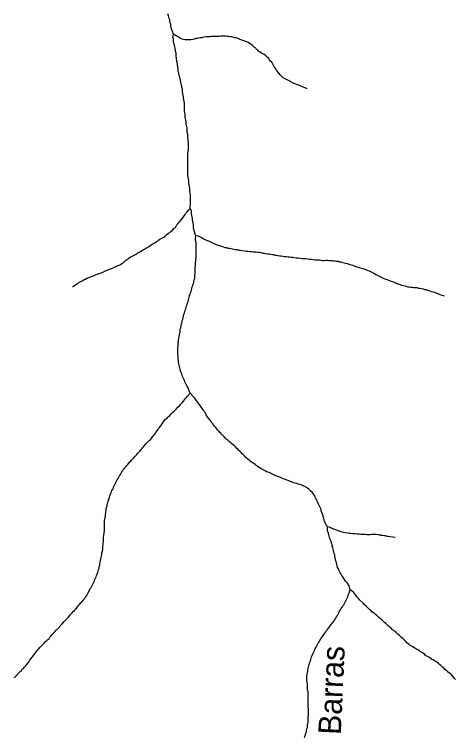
# Model space of a CAD drawing. Extents: x 652.3 to 678, y 7316.9 to 7344.9.
# Drawn here: x 673.932 to 675.495, y 7319.614 to 7322.173 of the extents above; entities that cross this region are included whole.
import ezdxf
from ezdxf.enums import TextEntityAlignment as Align

# ---------------------------------------------------------------- set-up
doc = ezdxf.new("R2010")
doc.units = 0
doc.header["$LTSCALE"] = 0.032
doc.layers.add('61', color=7, linetype='Continuous')
doc.layers.add('7', color=7, linetype='Continuous', lineweight=25)

msp = doc.modelspace()

# ---------------------------------------------------------------- linework, layer by layer
at = {"layer": '7'}
for p, q in [((674.5746, 7321.3896), (674.5741, 7321.3909)), ((674.5547, 7320.8302), (674.546, 7320.8517))]:
    msp.add_line(p, q, dxfattribs=at)
for points in [[(674.495, 7322.1025), (674.4879, 7322.1216), (674.4863, 7322.1327), (674.4855, 7322.1383), (674.4839, 7322.1431), (674.4831, 7322.1487), (674.4823, 7322.1542), (674.4807, 7322.159), (674.4791, 7322.1638), (674.4775, 7322.1685), (674.4759, 7322.1749)], [(674.5117, 7321.9816), (674.511, 7321.9871), (674.5102, 7321.9935), (674.5094, 7321.9991), (674.5078, 7322.0038), (674.5078, 7322.0094), (674.5062, 7322.0142), (674.5062, 7322.0198), (674.5054, 7322.0253), (674.5054, 7322.0309), (674.5046, 7322.0365), (674.503, 7322.042), (674.5022, 7322.0476), (674.5014, 7322.0532), (674.4998, 7322.0579), (674.499, 7322.0635), (674.4982, 7322.0691), (674.4958, 7322.0739), (674.4958, 7322.0794), (674.495, 7322.085), (674.4934, 7322.0906), (674.495, 7322.1025)], [(674.9693, 7321.9097), (674.9689, 7321.9098), (674.9645, 7321.9115), (674.9502, 7321.9171), (674.9454, 7321.9195), (674.9311, 7321.9243), (674.9215, 7321.929), (674.9168, 7321.9306), (674.9128, 7321.9338), (674.8985, 7321.941), (674.8937, 7321.9434), (674.8889, 7321.9458), (674.8849, 7321.9489), (674.8809, 7321.9521), (674.877, 7321.9553), (674.8738, 7321.9593), (674.8698, 7321.9633), (674.8603, 7321.9752), (674.8579, 7321.98), (674.8515, 7321.9895), (674.8483, 7321.9943), (674.8436, 7322.0038), (674.8396, 7322.0078), (674.8364, 7322.0126), (674.8332, 7322.0166), (674.8253, 7322.0245), (674.8213, 7322.0277), (674.8173, 7322.0309), (674.8077, 7322.0357), (674.803, 7322.0388), (674.7982, 7322.042), (674.7942, 7322.046), (674.7902, 7322.0492), (674.7871, 7322.0532), (674.7831, 7322.0564), (674.7791, 7322.0595), (674.7751, 7322.0635), (674.7703, 7322.0667), (674.7656, 7322.0699), (674.7608, 7322.0731), (674.756, 7322.0754), (674.7513, 7322.077), (674.7465, 7322.0794), (674.7417, 7322.081), (674.7322, 7322.0842), (674.7274, 7322.0866), (674.7178, 7322.0898), (674.7123, 7322.0906), (674.7075, 7322.0922), (674.7019, 7322.0937), (674.6956, 7322.0937), (674.6908, 7322.0953), (674.6852, 7322.0953), (674.6796, 7322.0961), (674.6629, 7322.0961), (674.6574, 7322.0953), (674.6295, 7322.0953), (674.6239, 7322.0937), (674.6128, 7322.0937), (674.6017, 7322.0922), (674.5961, 7322.0906), (674.5905, 7322.0906), (674.5857, 7322.089), (674.5802, 7322.0882), (674.5746, 7322.0874), (674.5698, 7322.0858), (674.5643, 7322.0842), (674.5587, 7322.0834), (674.5531, 7322.0826), (674.542, 7322.0826), (674.5364, 7322.0834), (674.5308, 7322.0842), (674.5261, 7322.0858), (674.5165, 7322.0906), (674.5094, 7322.0945), (674.5054, 7322.0977), (674.495, 7322.1025)], [(674.5547, 7321.4858), (674.5555, 7321.5049), (674.5563, 7321.5161), (674.5563, 7321.5216), (674.5563, 7321.5272), (674.5555, 7321.5328), (674.5547, 7321.5392), (674.5539, 7321.5447), (674.5531, 7321.5503), (674.5531, 7321.5559), (674.5523, 7321.5622), (674.5515, 7321.5678), (674.5499, 7321.5734), (674.5499, 7321.5789), (674.5499, 7321.5845), (674.5491, 7321.5901), (674.5476, 7321.5964), (674.5468, 7321.602), (674.5468, 7321.6076), (674.5468, 7321.6132), (674.5468, 7321.6187), (674.5468, 7321.6243), (674.5468, 7321.6299), (674.5468, 7321.6354), (674.5468, 7321.641), (674.5468, 7321.6466), (674.5468, 7321.6521), (674.5468, 7321.6577), (674.5468, 7321.6633), (674.5468, 7321.6689), (674.5468, 7321.6744), (674.5468, 7321.68), (674.5476, 7321.6872), (674.5484, 7321.6927), (674.5491, 7321.6983), (674.5484, 7321.7039), (674.5484, 7321.7094), (674.5484, 7321.715), (674.5484, 7321.7206), (674.5476, 7321.7261), (674.5476, 7321.7317), (674.5468, 7321.7373), (674.5468, 7321.7429), (674.546, 7321.7492), (674.5444, 7321.754), (674.5444, 7321.7596), (674.5436, 7321.7651), (674.5436, 7321.7707), (674.5428, 7321.7763), (674.5412, 7321.781), (674.5404, 7321.7866), (674.5404, 7321.7922), (674.5396, 7321.7978), (674.538, 7321.8025), (674.5372, 7321.8081), (674.5372, 7321.8137), (674.5364, 7321.8192), (674.5356, 7321.8248), (674.5348, 7321.8312), (674.5348, 7321.8367), (674.534, 7321.8423), (674.534, 7321.8479), (674.534, 7321.8535), (674.534, 7321.859), (674.5332, 7321.8646), (674.5316, 7321.8702), (674.5308, 7321.8757), (674.5308, 7321.8813), (674.53, 7321.8869), (674.5285, 7321.8916), (674.5277, 7321.8972), (674.5277, 7321.9028), (674.5269, 7321.9084), (674.5253, 7321.9131), (674.5245, 7321.9187), (674.5237, 7321.9243), (674.5221, 7321.929), (674.5213, 7321.9346), (674.5205, 7321.9402), (674.5189, 7321.945), (674.5181, 7321.9505), (674.5165, 7321.9553), (674.5149, 7321.9601), (674.5141, 7321.9656), (674.5125, 7321.9704), (674.5117, 7321.976), (674.5117, 7321.9816)], [(674.1379, 7321.2083), (674.1385, 7321.2088), (674.1425, 7321.2113), (674.1513, 7321.2169), (674.1561, 7321.2193), (674.1601, 7321.2225), (674.1648, 7321.2257), (674.1696, 7321.228), (674.1744, 7321.2304), (674.1784, 7321.2336), (674.1831, 7321.2352), (674.1879, 7321.2384), (674.2022, 7321.2432), (674.207, 7321.2455), (674.2118, 7321.2471), (674.2165, 7321.2487), (674.2213, 7321.2511), (674.2356, 7321.2559), (674.2404, 7321.2575), (674.2452, 7321.2599), (674.25, 7321.2623), (674.2547, 7321.2638), (674.2595, 7321.2662), (674.2643, 7321.2678), (674.2691, 7321.2702), (674.2738, 7321.2718), (674.2834, 7321.2766), (674.2882, 7321.2782), (674.2977, 7321.2829), (674.3025, 7321.2845), (674.3073, 7321.2869), (674.312, 7321.2901), (674.3168, 7321.2925), (674.3248, 7321.3004), (674.3287, 7321.3036), (674.3335, 7321.306), (674.3375, 7321.3092), (674.3423, 7321.3124), (674.347, 7321.3148), (674.351, 7321.318), (674.3653, 7321.3251), (674.3693, 7321.3283), (674.3789, 7321.3331), (674.3836, 7321.3363), (674.3884, 7321.3386), (674.3932, 7321.341), (674.3972, 7321.3442), (674.4067, 7321.349), (674.4107, 7321.3522), (674.4155, 7321.3554), (674.4202, 7321.3585), (674.425, 7321.3609), (674.429, 7321.3641), (674.4338, 7321.3673), (674.4385, 7321.3697), (674.4425, 7321.3729), (674.4473, 7321.376), (674.4521, 7321.3784), (674.4568, 7321.3816), (674.4616, 7321.384), (674.4656, 7321.3872), (674.4696, 7321.3904), (674.4736, 7321.3943), (674.4775, 7321.3975), (674.4823, 7321.4007), (674.4863, 7321.4039), (674.4903, 7321.4071), (674.4982, 7321.415), (674.5022, 7321.4182), (674.5054, 7321.4222), (674.5078, 7321.427), (674.511, 7321.4309), (674.5141, 7321.4357), (674.5181, 7321.4397), (674.5213, 7321.4437), (674.5285, 7321.4524), (674.5332, 7321.4596), (674.5364, 7321.4636), (674.5396, 7321.4683), (674.5428, 7321.4723), (674.5495, 7321.4805), (674.5547, 7321.4858)], [(674.5741, 7321.3909), (674.5674, 7321.411), (674.5667, 7321.4166), (674.5659, 7321.4222), (674.5659, 7321.4278), (674.5651, 7321.4333), (674.5635, 7321.4389), (674.5627, 7321.4445), (674.5627, 7321.45), (674.5619, 7321.4556), (674.5603, 7321.4604), (674.5595, 7321.466), (674.5595, 7321.4715), (674.5595, 7321.4771), (674.5547, 7321.4858)], [(674.546, 7320.8517), (674.5428, 7320.8565), (674.5404, 7320.8612), (674.538, 7320.866), (674.5356, 7320.8708), (674.534, 7320.8756), (674.5316, 7320.8803), (674.5293, 7320.8851), (674.5277, 7320.8899), (674.5261, 7320.8946), (674.5245, 7320.8994), (674.5229, 7320.9042), (674.5205, 7320.909), (674.5197, 7320.9145), (674.5181, 7320.9193), (674.5165, 7320.9249), (674.5157, 7320.9305), (674.5141, 7320.9352), (674.5133, 7320.9408), (674.5133, 7320.9464), (674.5125, 7320.9527), (674.5125, 7320.9583), (674.5117, 7320.9639), (674.511, 7320.9694), (674.511, 7320.975), (674.511, 7320.9806), (674.511, 7320.9862), (674.511, 7320.9917), (674.5117, 7320.9973), (674.5125, 7321.0029), (674.5125, 7321.0084), (674.5133, 7321.014), (674.5133, 7321.0196), (674.5141, 7321.0251), (674.5157, 7321.0299), (674.5165, 7321.0355), (674.5173, 7321.0411), (674.5189, 7321.0458), (674.5197, 7321.0514), (674.5197, 7321.057), (674.5213, 7321.0625), (674.5229, 7321.0681), (674.5229, 7321.0737), (674.5245, 7321.0785), (674.5261, 7321.0832), (674.5261, 7321.0888), (674.5285, 7321.0936), (674.5293, 7321.0991), (674.5308, 7321.1047), (674.5324, 7321.1095), (674.534, 7321.1151), (674.5356, 7321.1198), (674.5372, 7321.1254), (674.5388, 7321.1302), (674.5404, 7321.1357), (674.542, 7321.1405), (674.5444, 7321.1453), (674.5452, 7321.1509), (674.5476, 7321.1556), (674.5484, 7321.1612), (674.5499, 7321.166), (674.5515, 7321.1708), (674.5523, 7321.1763), (674.5547, 7321.1811), (674.5563, 7321.1867), (674.5579, 7321.1914), (674.5595, 7321.197), (674.5611, 7321.2018), (674.5619, 7321.2074), (674.5643, 7321.2121), (674.5651, 7321.2177), (674.5674, 7321.2225), (674.5674, 7321.228), (674.569, 7321.2328), (674.5706, 7321.2376), (674.5706, 7321.2432), (674.5706, 7321.2487), (674.5722, 7321.2535), (674.5722, 7321.2599), (674.5722, 7321.2654), (674.5722, 7321.271), (674.5722, 7321.2766), (674.573, 7321.2821), (674.5738, 7321.2877), (674.5738, 7321.2933), (674.5746, 7321.2989), (674.5746, 7321.3044), (674.5754, 7321.31), (674.5754, 7321.3156), (674.5754, 7321.3211), (674.5754, 7321.3267), (674.5762, 7321.3323), (674.5762, 7321.3378), (674.5762, 7321.3434), (674.5754, 7321.349), (674.5754, 7321.3546), (674.5754, 7321.3601), (674.5754, 7321.3657), (674.5738, 7321.3713), (674.573, 7321.3776), (674.5746, 7321.3896)], [(674.5746, 7321.3896), (674.5826, 7321.3888), (674.5873, 7321.3864), (674.5921, 7321.3832), (674.5969, 7321.3808), (674.604, 7321.3768), (674.6152, 7321.3721), (674.62, 7321.3705), (674.6247, 7321.3681), (674.6438, 7321.3585), (674.6534, 7321.3554), (674.659, 7321.3538), (674.6733, 7321.349), (674.678, 7321.3474), (674.6836, 7321.3466), (674.6884, 7321.345), (674.694, 7321.3442), (674.6995, 7321.3434), (674.7051, 7321.3426), (674.7099, 7321.341), (674.7154, 7321.3402), (674.721, 7321.3394), (674.7266, 7321.3378), (674.7322, 7321.337), (674.7377, 7321.3363), (674.7489, 7321.3347), (674.7544, 7321.3339), (674.76, 7321.3339), (674.7656, 7321.3331), (674.7719, 7321.3323), (674.7775, 7321.3315), (674.7886, 7321.3315), (674.795, 7321.3307), (674.8006, 7321.3299), (674.8069, 7321.3291), (674.8117, 7321.3275), (674.8173, 7321.3275), (674.8229, 7321.3259)], [(674.8229, 7321.3259), (674.8284, 7321.3251), (674.8348, 7321.3243), (674.8404, 7321.3235), (674.8451, 7321.3219), (674.8507, 7321.3219), (674.8555, 7321.3203), (674.8611, 7321.3203), (674.8658, 7321.3187), (674.8722, 7321.318), (674.8778, 7321.318), (674.8833, 7321.3164), (674.8889, 7321.3156), (674.8961, 7321.3148), (674.9016, 7321.314), (674.9072, 7321.314), (674.9128, 7321.3132), (674.9183, 7321.3124), (674.9247, 7321.3116), (674.9303, 7321.3108), (674.9359, 7321.3108), (674.947, 7321.3092), (674.9534, 7321.3084), (674.9589, 7321.3084), (674.9645, 7321.3076), (674.9717, 7321.3068), (674.9772, 7321.306), (674.9844, 7321.3052), (674.99, 7321.3044), (674.9963, 7321.3036), (675.0019, 7321.3028), (675.013, 7321.3028), (675.0186, 7321.302), (675.0242, 7321.3012), (675.0297, 7321.3012), (675.0353, 7321.302), (675.0409, 7321.302), (675.0465, 7321.3012), (675.052, 7321.3012), (675.0576, 7321.3004), (675.0632, 7321.2997), (675.0687, 7321.2997), (675.0735, 7321.2981), (675.0799, 7321.2981), (675.0846, 7321.2965), (675.0902, 7321.2957), (675.0958, 7321.2941), (675.1006, 7321.2925), (675.1061, 7321.2917), (675.1117, 7321.2901), (675.1212, 7321.2869), (675.1268, 7321.2861), (675.1316, 7321.2845), (675.1364, 7321.2821), (675.1459, 7321.279), (675.1507, 7321.2774), (675.165, 7321.2726), (675.1698, 7321.271), (675.1793, 7321.2678), (675.1841, 7321.2654), (675.1889, 7321.2638), (675.1937, 7321.2615), (675.1984, 7321.2599), (675.2032, 7321.2567), (675.208, 7321.2551), (675.2128, 7321.2519), (675.2223, 7321.2471), (675.2271, 7321.244), (675.2414, 7321.2368), (675.2557, 7321.232), (675.2613, 7321.2296), (675.2661, 7321.228), (675.2756, 7321.2249), (675.2852, 7321.2201), (675.2947, 7321.2169), (675.2995, 7321.2153), (675.3043, 7321.2137), (675.3098, 7321.2129), (675.3154, 7321.2113), (675.3202, 7321.2097), (675.3257, 7321.2081), (675.3313, 7321.2074), (675.3369, 7321.2066), (675.3424, 7321.2066), (675.3472, 7321.205), (675.3584, 7321.205), (675.3639, 7321.2034), (675.3695, 7321.2026), (675.3751, 7321.2018), (675.3806, 7321.2002), (675.3854, 7321.1986), (675.391, 7321.1978), (675.3966, 7321.1962), (675.4109, 7321.1914), (675.4157, 7321.1898), (675.4204, 7321.1883), (675.4252, 7321.1859), (675.4347, 7321.1827), (675.4395, 7321.1803), (675.4546, 7321.1755), (675.455, 7321.1754)], [(674.2571, 7320.4156), (674.2571, 7320.422), (674.2603, 7320.4316), (674.2603, 7320.4371), (674.2627, 7320.4419), (674.2635, 7320.4475), (674.2683, 7320.4618), (674.2699, 7320.4666), (674.273, 7320.4761), (674.2754, 7320.4809), (674.277, 7320.4857), (674.2802, 7320.4904), (674.2826, 7320.4952), (674.2842, 7320.5), (674.2866, 7320.5048), (674.2937, 7320.5191), (674.2961, 7320.5239), (674.2993, 7320.5286), (674.3041, 7320.5382), (674.3073, 7320.543), (674.3096, 7320.5477), (674.316, 7320.5573), (674.32, 7320.5613), (674.3232, 7320.566), (674.3264, 7320.57), (674.3295, 7320.574), (674.3335, 7320.578), (674.3399, 7320.5859), (674.3439, 7320.5899), (674.347, 7320.5939), (674.351, 7320.5979), (674.355, 7320.6018), (674.3582, 7320.6058), (674.3622, 7320.6098), (674.3653, 7320.6138), (674.3693, 7320.6177), (674.3757, 7320.6257), (674.3797, 7320.6297), (674.3828, 7320.6337), (674.386, 7320.6376), (674.39, 7320.6416), (674.3964, 7320.6496), (674.4083, 7320.6615), (674.4123, 7320.6647), (674.425, 7320.6806), (674.4282, 7320.6846), (674.4314, 7320.6894), (674.4346, 7320.6941), (674.4409, 7320.7021), (674.4441, 7320.7069), (674.4505, 7320.7148), (674.46, 7320.7291), (674.4664, 7320.7371), (674.4744, 7320.7451), (674.4783, 7320.7482), (674.4823, 7320.7522), (674.4855, 7320.7562), (674.4895, 7320.7594), (674.4934, 7320.7634), (674.4974, 7320.7673), (674.5014, 7320.7705), (674.5054, 7320.7745), (674.5086, 7320.7785), (674.5125, 7320.7825), (674.5165, 7320.7856), (674.5197, 7320.7896), (674.5237, 7320.7936), (674.5269, 7320.7976), (674.538, 7320.8119), (674.542, 7320.8159), (674.5452, 7320.8199), (674.5547, 7320.8302)], [(674.9661, 7320.4968), (674.9621, 7320.5), (674.9573, 7320.5016), (674.9526, 7320.504), (674.9478, 7320.5056), (674.943, 7320.5071), (674.9374, 7320.5087), (674.9319, 7320.5103), (674.9271, 7320.5119), (674.9215, 7320.5127), (674.9168, 7320.5151), (674.912, 7320.5167), (674.9072, 7320.5191), (674.9016, 7320.5207), (674.8969, 7320.5223), (674.8921, 7320.5247), (674.8873, 7320.5262), (674.8825, 7320.5278), (674.8778, 7320.5302), (674.873, 7320.5326), (674.8682, 7320.5342), (674.8634, 7320.5366), (674.8587, 7320.5382), (674.8539, 7320.5406), (674.8491, 7320.543), (674.8443, 7320.5445), (674.8396, 7320.5469), (674.8348, 7320.5493), (674.83, 7320.5509), (674.8253, 7320.5525), (674.8205, 7320.5557), (674.8157, 7320.5573), (674.8109, 7320.5597), (674.8062, 7320.5628), (674.8014, 7320.566), (674.7966, 7320.5684), (674.7926, 7320.5716), (674.7886, 7320.5748), (674.7847, 7320.578), (674.7807, 7320.5811), (674.7759, 7320.5835), (674.7719, 7320.5867), (674.7672, 7320.5899), (674.7632, 7320.5931), (674.7592, 7320.5971), (674.7552, 7320.6002), (674.7513, 7320.6042), (674.7473, 7320.6082), (674.7433, 7320.6122), (674.7393, 7320.6162), (674.7353, 7320.6201), (674.7314, 7320.6241), (674.7274, 7320.6281), (674.7234, 7320.6321), (674.7194, 7320.636), (674.7154, 7320.64), (674.7115, 7320.644), (674.7067, 7320.6472), (674.7027, 7320.6512), (674.6987, 7320.6551), (674.694, 7320.6583), (674.69, 7320.6623), (674.686, 7320.6663), (674.6812, 7320.6695), (674.6773, 7320.6734), (674.6733, 7320.6774), (674.6701, 7320.6814), (674.6661, 7320.6846), (674.6629, 7320.6886), (674.659, 7320.6925), (674.6558, 7320.6965), (674.6518, 7320.7005), (674.6486, 7320.7045), (674.6454, 7320.7085), (674.6414, 7320.7124), (674.6383, 7320.7172), (674.6351, 7320.722), (674.6319, 7320.726), (674.6287, 7320.7299), (674.6255, 7320.7347), (674.6223, 7320.7387), (674.6192, 7320.7427), (674.616, 7320.7474), (674.6128, 7320.7522), (674.6096, 7320.757), (674.608, 7320.7618), (674.6048, 7320.7657), (674.6017, 7320.7705), (674.5985, 7320.7753), (674.5953, 7320.7801), (674.5921, 7320.784), (674.5889, 7320.7888), (674.5857, 7320.7928), (674.5826, 7320.7968), (674.5794, 7320.8008), (674.5762, 7320.8055), (674.573, 7320.8095), (674.5698, 7320.8143), (674.5667, 7320.8183), (674.5547, 7320.8302)], [(675.0409, 7320.3568), (675.0398, 7320.3587), (675.0305, 7320.3759), (675.0297, 7320.3814), (675.0289, 7320.387), (675.0266, 7320.3918), (675.0258, 7320.3973), (675.0234, 7320.4021), (675.0218, 7320.4077), (675.0194, 7320.4125), (675.0186, 7320.418), (675.0162, 7320.4228), (675.0138, 7320.4276), (675.0122, 7320.4331), (675.0098, 7320.4379), (675.0075, 7320.4427), (675.0051, 7320.4475), (675.0035, 7320.4522), (675.0003, 7320.457), (674.9979, 7320.4618), (674.9963, 7320.4666), (674.9931, 7320.4713), (674.99, 7320.4761), (674.9868, 7320.4801), (674.9828, 7320.4833), (674.9788, 7320.4865), (674.9748, 7320.4904), (674.9701, 7320.4936), (674.9661, 7320.4968)], [(673.9316, 7319.8223), (673.9318, 7319.8226), (673.9373, 7319.8284), (673.9484, 7319.8404), (673.9524, 7319.8443), (673.9564, 7319.8483), (673.9595, 7319.8523), (673.9635, 7319.8555), (673.9667, 7319.8595), (673.9707, 7319.8634), (673.9739, 7319.8674), (673.9802, 7319.8754), (673.9834, 7319.8801), (673.9866, 7319.8849), (673.9898, 7319.8897), (673.9993, 7319.9016), (674.0025, 7319.9056), (674.0057, 7319.9104), (674.0089, 7319.9144), (674.0121, 7319.9183), (674.0152, 7319.9223), (674.0232, 7319.9303), (674.0264, 7319.9343), (674.0383, 7319.9462), (674.0423, 7319.9502), (674.0463, 7319.9541), (674.0502, 7319.9573), (674.0542, 7319.9613), (674.0574, 7319.9661), (674.0606, 7319.9701), (674.0646, 7319.974), (674.0678, 7319.978), (674.0757, 7319.986), (674.0789, 7319.9899), (674.0908, 7320.0019), (674.094, 7320.0059), (674.0972, 7320.0098), (674.1012, 7320.013), (674.1075, 7320.021), (674.1115, 7320.025), (674.1147, 7320.0289), (674.1227, 7320.0369), (674.129, 7320.0449), (674.133, 7320.0488), (674.1362, 7320.0528), (674.1402, 7320.0568), (674.1441, 7320.0608), (674.1473, 7320.0647), (674.1513, 7320.0687), (674.1577, 7320.0767), (674.1616, 7320.0807), (674.168, 7320.0886), (674.1712, 7320.0926), (674.1752, 7320.0966), (674.1784, 7320.1006), (674.1815, 7320.1053), (674.1847, 7320.1093), (674.1879, 7320.1141), (674.1903, 7320.1189), (674.1935, 7320.1236), (674.1959, 7320.1284), (674.199, 7320.1332), (674.2006, 7320.1379), (674.2038, 7320.1419), (674.211, 7320.1562), (674.2126, 7320.161), (674.215, 7320.1658), (674.2165, 7320.1706), (674.2189, 7320.1753), (674.2213, 7320.1801), (674.2229, 7320.1849), (674.2253, 7320.1897), (674.2269, 7320.1952), (674.2285, 7320.2), (674.2301, 7320.2056), (674.2317, 7320.2104), (674.2325, 7320.2159), (674.2341, 7320.2207), (674.2348, 7320.2263), (674.2356, 7320.2318), (674.2372, 7320.2366), (674.2388, 7320.2478), (674.2404, 7320.2533), (674.2412, 7320.2597), (674.242, 7320.2653), (674.2436, 7320.2708), (674.2444, 7320.2764), (674.2444, 7320.2883), (674.246, 7320.2931), (674.246, 7320.2987), (674.2476, 7320.3035), (674.2476, 7320.3202), (674.2484, 7320.3257), (674.25, 7320.3369), (674.2508, 7320.3424), (674.2508, 7320.3767), (674.2524, 7320.3878), (674.2539, 7320.3926), (674.2539, 7320.3981), (674.2555, 7320.4093), (674.2571, 7320.4156)], [(675.2815, 7320.3189), (675.2811, 7320.319), (675.2732, 7320.3202), (675.2629, 7320.3218), (675.2581, 7320.3233), (675.2525, 7320.3233), (675.247, 7320.3249), (675.2414, 7320.3249), (675.2366, 7320.3265), (675.2311, 7320.3265), (675.2263, 7320.3281), (675.2207, 7320.3281), (675.2151, 7320.3297), (675.1984, 7320.3297), (675.1929, 7320.3289), (675.1817, 7320.3289), (675.1761, 7320.3297), (675.1594, 7320.3297), (675.1539, 7320.3305), (675.1483, 7320.3305), (675.1372, 7320.3321), (675.1308, 7320.3321), (675.1244, 7320.3337), (675.1181, 7320.3337), (675.1125, 7320.3345), (675.1053, 7320.3361), (675.0982, 7320.3369), (675.0934, 7320.3385), (675.0791, 7320.3432), (675.0743, 7320.3448), (675.06, 7320.3496), (675.0504, 7320.3544), (675.0457, 7320.356), (675.0409, 7320.3568)], [(675.122, 7320.1332), (675.1181, 7320.1483), (675.1125, 7320.157), (675.1085, 7320.161), (675.1053, 7320.165), (675.1021, 7320.1698), (675.099, 7320.1745), (675.0958, 7320.1793), (675.0926, 7320.1841), (675.0894, 7320.1889), (675.0862, 7320.1936), (675.0838, 7320.1984), (675.0823, 7320.2032), (675.0799, 7320.208), (675.0775, 7320.2127), (675.0759, 7320.2191), (675.0743, 7320.2239), (675.0735, 7320.2295), (675.0719, 7320.2342), (675.0703, 7320.239), (675.0695, 7320.2454), (675.0679, 7320.2501), (675.0671, 7320.2573), (675.0655, 7320.2621), (675.064, 7320.2676), (675.0632, 7320.2732), (675.0616, 7320.278), (675.0608, 7320.2844), (675.0584, 7320.2891), (675.0576, 7320.2947), (675.0552, 7320.2995), (675.0544, 7320.305), (675.052, 7320.3098), (675.0504, 7320.3146), (675.0488, 7320.3194), (675.0472, 7320.3241), (675.0457, 7320.3289), (675.0449, 7320.3345), (675.0425, 7320.3393), (675.0417, 7320.3448), (675.0409, 7320.3568)], [(675.0289, 7319.9756), (675.0321, 7319.9804), (675.0353, 7319.9852), (675.0385, 7319.9892), (675.0417, 7319.9931), (675.0449, 7319.9979), (675.048, 7320.0027), (675.0512, 7320.0067), (675.0544, 7320.0106), (675.0576, 7320.0154), (675.0616, 7320.0194), (675.0648, 7320.0242), (675.0679, 7320.0289), (675.0711, 7320.0337), (675.0735, 7320.0385), (675.0767, 7320.0433), (675.0791, 7320.048), (675.0815, 7320.0528), (675.0846, 7320.0576), (675.0878, 7320.0624), (675.0902, 7320.0671), (675.0934, 7320.0719), (675.0958, 7320.0767), (675.099, 7320.0807), (675.1014, 7320.0854), (675.1045, 7320.0902), (675.1061, 7320.095), (675.1093, 7320.099), (675.1117, 7320.1037), (675.1133, 7320.1085), (675.1149, 7320.1133), (675.1165, 7320.1181), (675.1181, 7320.1228), (675.122, 7320.1332)], [(675.4955, 7319.816), (675.495, 7319.8165), (675.4928, 7319.8189), (675.4817, 7319.8308), (675.4785, 7319.8348), (675.4745, 7319.838), (675.4706, 7319.8412), (675.4666, 7319.8451), (675.4618, 7319.8483), (675.4578, 7319.8515), (675.4546, 7319.8555), (675.4507, 7319.8587), (675.4467, 7319.8618), (675.4427, 7319.8658), (675.4387, 7319.869), (675.4347, 7319.873), (675.4308, 7319.8762), (675.426, 7319.8793), (675.4212, 7319.8825), (675.4164, 7319.8857), (675.4117, 7319.8873), (675.4077, 7319.8913), (675.4029, 7319.8937), (675.3989, 7319.8969), (675.3942, 7319.8992), (675.3894, 7319.9016), (675.3854, 7319.9056), (675.3806, 7319.9088), (675.3759, 7319.912), (675.3711, 7319.9144), (675.3671, 7319.9175), (675.3623, 7319.9207), (675.3576, 7319.9231), (675.3536, 7319.9263), (675.3488, 7319.9287), (675.344, 7319.9319), (675.3345, 7319.9366), (675.3305, 7319.9398), (675.3265, 7319.943), (675.3226, 7319.9462), (675.3194, 7319.951), (675.3154, 7319.9541), (675.3122, 7319.9581), (675.3082, 7319.9613), (675.3043, 7319.9653), (675.3003, 7319.9685), (675.2963, 7319.9716), (675.2923, 7319.9756), (675.2883, 7319.9788), (675.2844, 7319.982), (675.2804, 7319.986), (675.2764, 7319.9892), (675.2724, 7319.9923), (675.2684, 7319.9963), (675.2645, 7319.9995), (675.2605, 7320.0035), (675.2565, 7320.0067), (675.2486, 7320.0146), (675.2438, 7320.0178), (675.2358, 7320.0258), (675.2318, 7320.0289), (675.2279, 7320.0321), (675.2239, 7320.0361), (675.2199, 7320.0393), (675.2159, 7320.0425), (675.212, 7320.0464), (675.208, 7320.0496), (675.204, 7320.0528), (675.1992, 7320.056), (675.1952, 7320.06), (675.1913, 7320.0632), (675.1873, 7320.0671), (675.1833, 7320.0711), (675.1793, 7320.0743), (675.1714, 7320.0822), (675.1674, 7320.0862), (675.1555, 7320.0982), (675.1523, 7320.1021), (675.1459, 7320.1093), (675.1403, 7320.1165), (675.1372, 7320.1204), (675.134, 7320.1252), (675.122, 7320.1332)], [(674.9605, 7319.6088), (674.9613, 7319.6144), (674.9637, 7319.62), (674.9645, 7319.6255), (674.9669, 7319.6303), (674.9669, 7319.6359), (674.9677, 7319.6414), (674.9701, 7319.6462), (674.9701, 7319.6518), (674.9709, 7319.6574), (674.9725, 7319.6621), (674.9732, 7319.6677), (674.9732, 7319.6733), (674.9732, 7319.6788), (674.9732, 7319.6844), (674.974, 7319.69), (674.974, 7319.6955), (674.974, 7319.7011), (674.974, 7319.7067), (674.974, 7319.7123), (674.9732, 7319.7178), (674.9732, 7319.7234), (674.9732, 7319.729), (674.9732, 7319.7345), (674.9732, 7319.7401), (674.9732, 7319.7457), (674.9732, 7319.7512), (674.9732, 7319.7568), (674.9732, 7319.7624), (674.9732, 7319.768), (674.9725, 7319.7735), (674.9709, 7319.7783), (674.9709, 7319.7839), (674.9701, 7319.7894), (674.9701, 7319.795), (674.9701, 7319.8006), (674.9693, 7319.8061), (674.9685, 7319.8117), (674.9685, 7319.8173), (674.9685, 7319.8229), (674.9685, 7319.8284), (674.9693, 7319.834), (674.9701, 7319.8404), (674.9717, 7319.8451), (674.9717, 7319.8507), (674.9725, 7319.8563), (674.974, 7319.861), (674.9748, 7319.8666), (674.9772, 7319.8714), (674.9788, 7319.877), (674.9812, 7319.8817), (674.982, 7319.8873), (674.9836, 7319.8921), (674.9852, 7319.8969), (674.9876, 7319.9016), (674.9892, 7319.9064), (674.9915, 7319.9112), (674.9939, 7319.916), (674.9963, 7319.9207), (674.9979, 7319.9255), (675.0011, 7319.9303), (675.0035, 7319.935), (675.0059, 7319.9398), (675.0083, 7319.9446), (675.0114, 7319.9494), (675.0138, 7319.9541), (675.017, 7319.9581), (675.0194, 7319.9629), (675.0226, 7319.9669), (675.0258, 7319.9716), (675.0289, 7319.9756)]]:
    msp.add_lwpolyline(points, dxfattribs=at)

# ---------------------------------------------------------------- texts
at = {"layer": '61'}
msp.add_text('Barras', height=0.08, rotation=87.4, dxfattribs=at).set_placement((675.0957, 7319.776), align=Align.CENTER)

doc.saveas('drawing.dxf')
